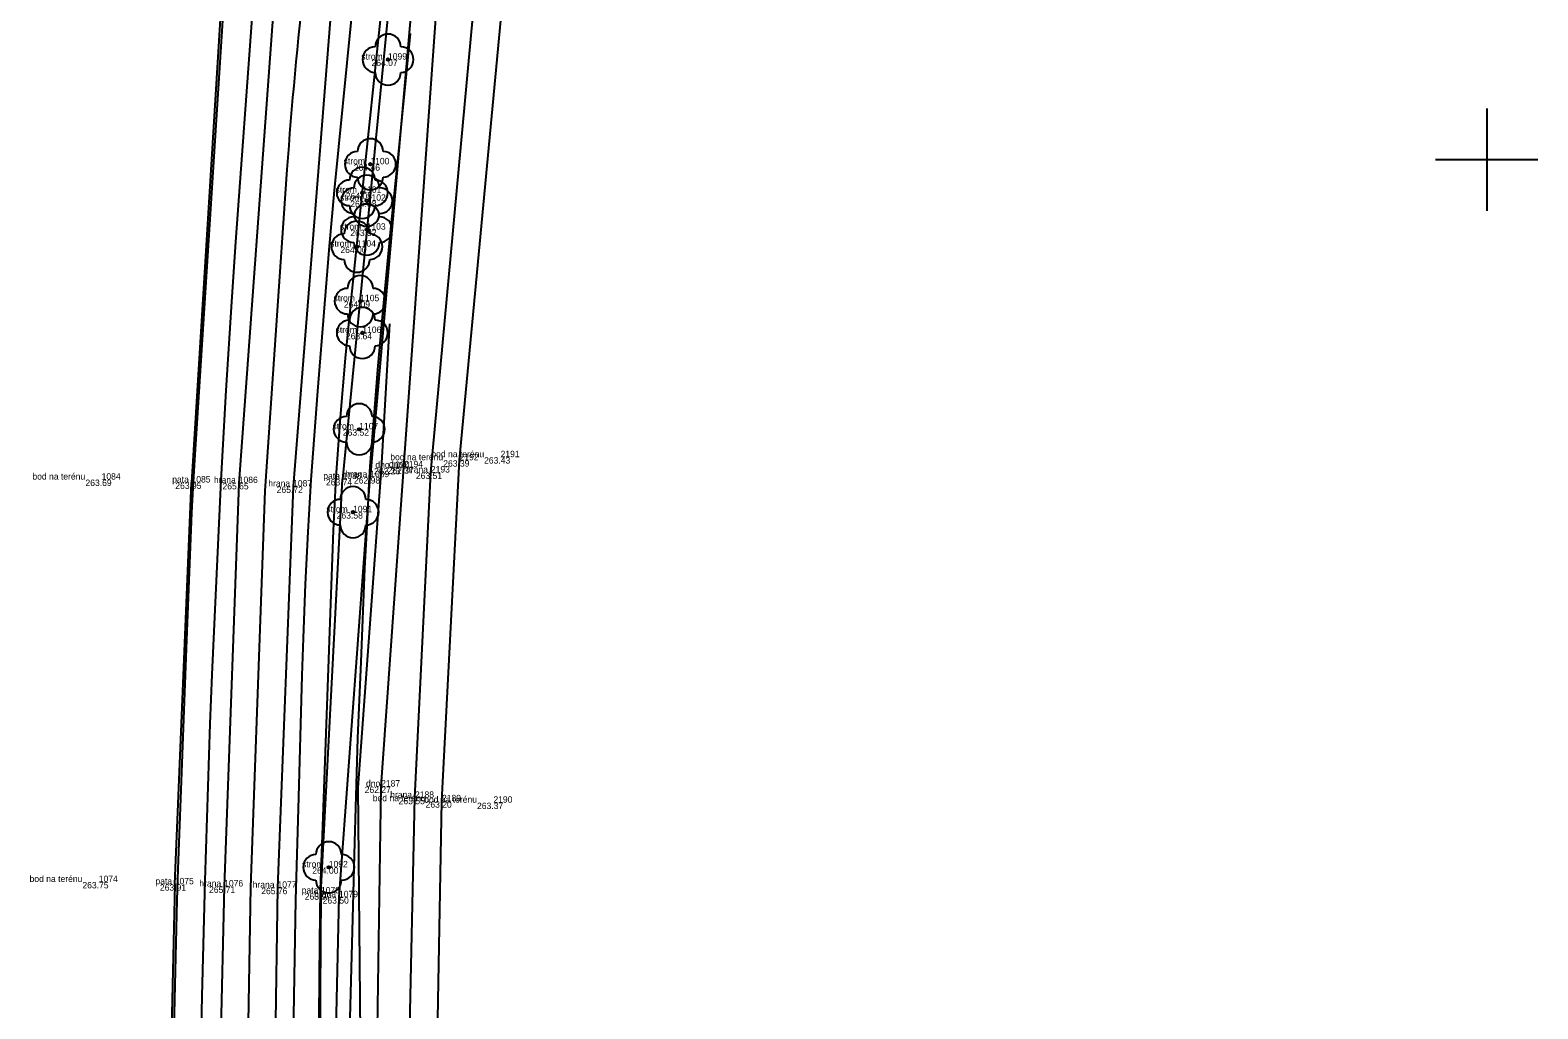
# Model space of a CAD drawing. Extents: x -567962 to -566460, y -1093720 to -1089838.
# Drawn here: x -567313.9 to -567196, y -1091466.4 to -1091389.9 of the extents above; entities that cross this region are included whole.
import ezdxf

# ---------------------------------------------------------------- set-up
doc = ezdxf.new("R2010")
doc.units = 0
for name, color, linetype in [('0_osa hráze', 7, 'Continuous'), ('bod_znacka', 7, 'Continuous'), ('cislo_bodu', 7, 'Continuous'), ('ctvercova_sit', 7, 'Continuous'), ('Doměření - kraj pole', 7, 'Continuous'), ('hlavni_vrst', 7, 'Continuous'), ('hrana_L', 7, 'Continuous'), ('kod_bodu', 7, 'Continuous'), ('norm_vrst', 7, 'Continuous'), ('stromy', 7, 'Continuous'), ('vyska_bodu', 7, 'Continuous')]:
    doc.layers.add(name, color=color, linetype=linetype)

msp = doc.modelspace()

# ---------------------------------------------------------------- linework, layer by layer
at = {"layer": '0_osa hráze'}
msp.add_lwpolyline([(-567293.79, -1091400.76), (-567295.51, -1091425.87), (-567296.63, -1091456.85), (-567298.73, -1091577.56)], dxfattribs=at)
msp.add_arc((-566984.79, -1091422.2), 309.74, 173.2556, 176.0314, dxfattribs=at)
at = {"layer": 'bod_znacka'}
for p, q in [((-567285.89, -1091392.18), (-567285.89, -1091392.18)), ((-567287.27, -1091400.36), (-567287.27, -1091400.36)), ((-567287.9, -1091402.59), (-567287.9, -1091402.59)), ((-567287.55, -1091403.21), (-567287.55, -1091403.21)), ((-567287.56, -1091405.47), (-567287.56, -1091405.47)), ((-567288.32, -1091406.8), (-567288.32, -1091406.8)), ((-567288.06, -1091411.06), (-567288.06, -1091411.06)), ((-567287.9, -1091413.54), (-567287.9, -1091413.54)), ((-567288.14, -1091421.07), (-567288.14, -1091421.07)), ((-567285.7, -1091424.09), (-567285.7, -1091424.09)), ((-567284.64, -1091424.04), (-567284.64, -1091424.04)), ((-567280.3, -1091423.49), (-567280.3, -1091423.49)), ((-567277.09, -1091423.25), (-567277.09, -1091423.25)), ((-567308.28, -1091425), (-567308.28, -1091425)), ((-567301.25, -1091425.23), (-567301.25, -1091425.23)), ((-567297.56, -1091425.27), (-567297.56, -1091425.27)), ((-567289.44, -1091424.96), (-567289.44, -1091424.96)), ((-567287.28, -1091424.81), (-567287.28, -1091424.81)), ((-567282.54, -1091424.45), (-567282.54, -1091424.45)), ((-567293.31, -1091425.54), (-567293.31, -1091425.54)), ((-567288.62, -1091427.55), (-567288.62, -1091427.55)), ((-567286.43, -1091448.99), (-567286.43, -1091448.99)), ((-567283.78, -1091449.87), (-567283.78, -1091449.87)), ((-567281.67, -1091450.14), (-567281.67, -1091450.14)), ((-567277.65, -1091450.25), (-567277.65, -1091450.25)), ((-567290.52, -1091455.3), (-567290.52, -1091455.3)), ((-567308.5, -1091456.45), (-567308.5, -1091456.45)), ((-567302.56, -1091456.63), (-567302.56, -1091456.63)), ((-567298.7, -1091456.8), (-567298.7, -1091456.8)), ((-567294.53, -1091456.9), (-567294.53, -1091456.9)), ((-567291.13, -1091457.34), (-567291.13, -1091457.34)), ((-567289.72, -1091457.64), (-567289.72, -1091457.64))]:
    msp.add_line(p, q, dxfattribs=at)
at = {"layer": 'ctvercova_sit'}
for points in [[(-567200, -1091396), (-567200, -1091404)], [(-567196, -1091400), (-567204, -1091400)]]:
    msp.add_lwpolyline(points, dxfattribs=at)
at = {"layer": 'Doměření - kraj pole'}
msp.add_lwpolyline([(-567257.48, -1091769.85), (-567265.06, -1091716.84), (-567271.4, -1091685.39), (-567277.57, -1091653.16), (-567282.77, -1091606.25), (-567283.94, -1091587.31), (-567282.43, -1091491.21), (-567281.67, -1091450.14), (-567280.3, -1091423.49), (-567276.56, -1091383.56), (-567271.12, -1091342.8), (-567265.61, -1091306.08), (-567257.61, -1091256.68), (-567252.66, -1091230.21)], dxfattribs=at)
at = {"layer": 'hlavni_vrst'}
for points in [[(-567296.48, -1091388.25), (-567297.8, -1091406.42), (-567298.12, -1091411.1), (-567298.56, -1091418.03), (-567298.97, -1091425.05), (-567299.67, -1091440.23), (-567299.83, -1091444.08), (-567300.22, -1091456.34), (-567300.44, -1091465.38), (-567300.57, -1091471.53), (-567300.7, -1091479.58), (-567300.85, -1091489.48), (-567301.51, -1091523.87), (-567301.53, -1091525.02), (-567301.64, -1091528.6), (-567301.92, -1091540.53), (-567301.97, -1091543.52)], [(-567294.98, -1091547.06), (-567294.72, -1091538.24), (-567294.27, -1091524.34), (-567294.14, -1091517.89), (-567293.88, -1091502.59), (-567293.7, -1091489.61), (-567293.34, -1091471.38), (-567293.09, -1091457.86), (-567292.85, -1091449.82), (-567292.6, -1091440.32), (-567292.5, -1091437.4), (-567292.33, -1091433.18), (-567292.13, -1091429.09), (-567291.9, -1091425.02), (-567291.37, -1091418.1), (-567290.83, -1091411.26), (-567290.46, -1091406.77), (-567290.07, -1091402.41), (-567288.75, -1091389.03)]]:
    msp.add_lwpolyline(points, dxfattribs=at)
at = {"layer": 'hrana_L'}
for p, q in [((-567283.99, -1091387.39), (-567287.28, -1091424.81)), ((-567298.96, -1091388.18), (-567301.25, -1091425.23)), ((-567294.87, -1091388.51), (-567297.56, -1091425.27)), ((-567290.42, -1091389.11), (-567293.31, -1091425.54)), ((-567285.94, -1091388.99), (-567289.44, -1091424.96)), ((-567302.56, -1091456.63), (-567301.25, -1091425.23)), ((-567297.56, -1091425.27), (-567298.7, -1091456.8)), ((-567291.13, -1091457.34), (-567289.44, -1091424.96)), ((-567289.72, -1091457.64), (-567287.28, -1091424.81)), ((-567293.31, -1091425.54), (-567294.53, -1091456.9)), ((-567302.56, -1091456.63), (-567303.32, -1091489.56)), ((-567298.7, -1091456.8), (-567299.47, -1091489.79)), ((-567294.53, -1091456.9), (-567295.04, -1091489.95)), ((-567291.13, -1091457.34), (-567291.4, -1091489.34)), ((-567290.43, -1091490.23), (-567289.72, -1091457.64))]:
    msp.add_line(p, q, dxfattribs=at)
for points in [[(-567259.54, -1091769.58), (-567267.06, -1091718.28), (-567273.44, -1091685.18), (-567279.67, -1091653.51), (-567285.46, -1091606.32), (-567286.7, -1091587.2), (-567284.69, -1091490.41), (-567283.78, -1091449.87), (-567282.54, -1091424.45), (-567278.78, -1091383.78), (-567273.15, -1091341.64), (-567267.14, -1091305.78), (-567258.66, -1091256.72), (-567254.64, -1091232.23), (-567240.38, -1091148.66)], [(-567261.58, -1091768.89), (-567269.05, -1091719.43), (-567275.12, -1091685.08), (-567281.42, -1091653.8), (-567287.56, -1091606.69), (-567288.64, -1091587.56), (-567287.08, -1091491.97), (-567286.43, -1091448.99), (-567284.64, -1091424.04), (-567281.88, -1091385.27), (-567275.66, -1091341.93), (-567269.17, -1091305.64), (-567264.83, -1091271.45)], [(-567287.83, -1091490.38), (-567288.21, -1091449.06), (-567286.41, -1091424.16), (-567285.76, -1091412.82)]]:
    msp.add_lwpolyline(points, dxfattribs=at)
at = {"layer": 'norm_vrst'}
for points in [[(-567298.82, -1091389.12), (-567301.03, -1091423.47), (-567301.16, -1091425.64), (-567301.25, -1091427.6), (-567301.64, -1091437.53), (-567302.32, -1091455.44), (-567302.4, -1091457.88), (-567303.14, -1091488.89), (-567303.65, -1091506.16), (-567304.1, -1091523.18), (-567304.16, -1091524.66), (-567304.35, -1091528.44), (-567304.58, -1091533.44), (-567304.64, -1091536.19), (-567304.63, -1091537.73), (-567304.54, -1091541.65), (-567304.53, -1091542.47), (-567304.54, -1091543.98)], [(-567292.99, -1091550.57), (-567292.33, -1091532.29), (-567292.07, -1091525.57), (-567292.01, -1091523.42), (-567291.97, -1091521.23), (-567291.77, -1091501.42), (-567291.58, -1091486.31), (-567291.28, -1091466.97), (-567291.21, -1091461.1), (-567291.18, -1091457.03), (-567291.01, -1091452.78), (-567290.32, -1091433.26), (-567290.15, -1091428.99), (-567289.95, -1091424.81), (-567289.61, -1091420.14), (-567289.2, -1091415.5), (-567288.76, -1091411.03), (-567287.85, -1091402.24), (-567286.48, -1091389.11)], [(-567288.92, -1091469.99), (-567288.62, -1091458.34), (-567288.49, -1091453.34), (-567288.24, -1091445.22), (-567288, -1091439.25), (-567287.69, -1091431.95), (-567287.53, -1091428.63), (-567287.44, -1091427.02), (-567287.36, -1091425.27), (-567287.28, -1091423.97), (-567287.11, -1091421.69), (-567286.88, -1091418.74), (-567286.69, -1091416.41), (-567286.27, -1091411.74), (-567285.66, -1091405.42), (-567285.09, -1091399.85), (-567284.12, -1091390.14)]]:
    msp.add_lwpolyline(points, dxfattribs=at)
at = {"layer": 'stromy'}
for centre in [(-567285.89, -1091392.18), (-567287.27, -1091400.36), (-567287.9, -1091402.59), (-567287.55, -1091403.21), (-567287.56, -1091405.47), (-567288.32, -1091406.8), (-567288.06, -1091411.06), (-567287.9, -1091413.54), (-567288.14, -1091421.07), (-567288.62, -1091427.55), (-567290.52, -1091455.3)]:
    msp.add_circle(centre, 0.1, dxfattribs=at)
for centre, start, end in [((-567286.89, -1091392.18), 90, 270), ((-567285.89, -1091391.18), 0, 180), ((-567284.89, -1091392.18), 270, 90), ((-567285.89, -1091393.18), 180, 0), ((-567287.27, -1091399.36), 0, 180), ((-567288.27, -1091400.36), 90, 270), ((-567286.27, -1091400.36), 270, 90), ((-567287.9, -1091401.59), 0, 180), ((-567288.9, -1091402.59), 90, 270), ((-567287.55, -1091402.21), 0, 180), ((-567287.27, -1091401.36), 180, 0), ((-567286.9, -1091402.59), 270, 90), ((-567288.55, -1091403.21), 90, 270), ((-567286.55, -1091403.21), 270, 90), ((-567287.9, -1091403.59), 180, 0), ((-567287.56, -1091404.47), 0, 180), ((-567287.55, -1091404.21), 180, 0), ((-567288.56, -1091405.47), 90, 270), ((-567288.32, -1091405.8), 0, 180), ((-567286.56, -1091405.47), 270, 90), ((-567289.32, -1091406.8), 90, 270), ((-567287.56, -1091406.47), 180, 0), ((-567287.32, -1091406.8), 270, 90), ((-567288.32, -1091407.8), 180, 0), ((-567289.06, -1091411.06), 90, 270), ((-567288.06, -1091410.06), 0, 180), ((-567287.06, -1091411.06), 270, 90), ((-567288.06, -1091412.06), 180, 0), ((-567287.9, -1091412.54), 0, 180), ((-567288.9, -1091413.54), 90, 270), ((-567286.9, -1091413.54), 270, 90), ((-567287.9, -1091414.54), 180, 0), ((-567288.14, -1091420.07), 0, 180), ((-567289.14, -1091421.07), 90, 270), ((-567287.14, -1091421.07), 270, 90), ((-567288.14, -1091422.07), 180, 0), ((-567289.62, -1091427.55), 90, 270), ((-567288.62, -1091426.55), 0, 180), ((-567287.62, -1091427.55), 270, 90), ((-567288.62, -1091428.55), 180, 0), ((-567290.52, -1091454.3), 0, 180), ((-567291.52, -1091455.3), 90, 270), ((-567289.52, -1091455.3), 270, 90), ((-567290.52, -1091456.3), 180, 0)]:
    msp.add_arc(centre, 1, start, end, dxfattribs=at)

# ---------------------------------------------------------------- texts
at = {"layer": 'cislo_bodu'}
for s, p in [('1099', (-567285.89, -1091392.18)), ('1100', (-567287.27, -1091400.36)), ('1101', (-567287.9, -1091402.59)), ('1102', (-567287.55, -1091403.21)), ('1103', (-567287.56, -1091405.47)), ('1104', (-567288.32, -1091406.8)), ('1105', (-567288.06, -1091411.06)), ('1106', (-567287.9, -1091413.54)), ('1107', (-567288.14, -1091421.07)), ('2192', (-567280.3, -1091423.49)), ('2191', (-567277.09, -1091423.25)), ('1089', (-567287.28, -1091424.81)), ('1090', (-567285.7, -1091424.09)), ('2194', (-567284.64, -1091424.04)), ('2193', (-567282.54, -1091424.45)), ('1084', (-567308.28, -1091425)), ('1085', (-567301.25, -1091425.23)), ('1086', (-567297.56, -1091425.27)), ('1087', (-567293.31, -1091425.54)), ('1088', (-567289.44, -1091424.96)), ('1091', (-567288.62, -1091427.55)), ('2187', (-567286.43, -1091448.99)), ('2188', (-567283.78, -1091449.87)), ('2189', (-567281.67, -1091450.14)), ('2190', (-567277.65, -1091450.25)), ('1092', (-567290.52, -1091455.3)), ('1074', (-567308.5, -1091456.45)), ('1075', (-567302.56, -1091456.63)), ('1076', (-567298.7, -1091456.8)), ('1077', (-567294.53, -1091456.9)), ('1078', (-567291.13, -1091457.34)), ('1079', (-567289.72, -1091457.64))]:
    msp.add_text(s, height=0.5, dxfattribs=at).set_placement(p)
at = {"layer": 'kod_bodu'}
for s, p in [('strom', (-567287.98, -1091392.18)), ('strom', (-567289.36, -1091400.36)), ('strom', (-567289.99, -1091402.59)), ('strom', (-567289.64, -1091403.21)), ('strom', (-567289.65, -1091405.47)), ('strom', (-567290.41, -1091406.8)), ('strom', (-567290.15, -1091411.06)), ('strom', (-567289.99, -1091413.54)), ('strom', (-567290.23, -1091421.07)), ('bod na terénu', (-567285.71, -1091423.49)), ('bod na terénu', (-567282.5, -1091423.25)), ('hrana', (-567289.22, -1091424.81)), ('dno', (-567286.88, -1091424.09)), ('dno', (-567285.82, -1091424.04)), ('hrana', (-567284.48, -1091424.45)), ('bod na terénu', (-567313.69, -1091425)), ('pata', (-567302.76, -1091425.23)), ('hrana', (-567299.5, -1091425.27)), ('hrana', (-567295.25, -1091425.54)), ('pata', (-567290.95, -1091424.96)), ('strom', (-567290.71, -1091427.55)), ('dno', (-567287.61, -1091448.99)), ('bod na terénu', (-567287.08, -1091450.14)), ('hrana', (-567285.72, -1091449.87)), ('bod na terénu', (-567283.06, -1091450.25)), ('strom', (-567292.61, -1091455.3)), ('bod na terénu', (-567313.91, -1091456.45)), ('pata', (-567304.07, -1091456.63)), ('hrana', (-567300.64, -1091456.8)), ('hrana', (-567296.47, -1091456.9)), ('pata', (-567292.64, -1091457.34)), ('hrana', (-567291.66, -1091457.64))]:
    msp.add_text(s, height=0.5, dxfattribs=at).set_placement(p)
at = {"layer": 'vyska_bodu'}
for s, p in [('264.07', (-567287.18, -1091392.68)), ('264.46', (-567288.56, -1091400.86)), ('264.08', (-567289.19, -1091403.09)), ('264.08', (-567288.84, -1091403.71)), ('263.92', (-567288.83, -1091405.97)), ('264.00', (-567289.61, -1091407.3)), ('264.09', (-567289.34, -1091411.56)), ('263.64', (-567289.18, -1091414.04)), ('263.52', (-567289.42, -1091421.57)), ('262.23', (-567286.98, -1091424.59)), ('262.37', (-567285.92, -1091424.54)), ('263.39', (-567281.57, -1091423.99)), ('263.43', (-567278.38, -1091423.75)), ('263.69', (-567309.54, -1091425.5)), ('263.95', (-567302.52, -1091425.73)), ('265.65', (-567298.83, -1091425.77)), ('263.74', (-567290.74, -1091425.46)), ('262.98', (-567288.55, -1091425.31)), ('263.51', (-567283.71, -1091424.95)), ('265.72', (-567294.59, -1091426.04)), ('263.58', (-567289.9, -1091428.05)), ('262.27', (-567287.71, -1091449.49)), ('263.55', (-567285.06, -1091450.37)), ('263.20', (-567282.95, -1091450.64)), ('263.37', (-567278.93, -1091450.75)), ('264.00', (-567291.81, -1091455.8)), ('263.75', (-567309.78, -1091456.95)), ('263.91', (-567303.72, -1091457.13)), ('265.71', (-567299.88, -1091457.3)), ('265.76', (-567295.8, -1091457.4)), ('263.97', (-567292.4, -1091457.84)), ('263.50', (-567291, -1091458.14))]:
    msp.add_text(s, height=0.5, dxfattribs=at).set_placement(p)

doc.saveas('drawing.dxf')
